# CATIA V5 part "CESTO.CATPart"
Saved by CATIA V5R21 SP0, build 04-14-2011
Part number: CESTO
Bounding box of the stored display mesh (mm): x -219.998 to 219.998, y -219.997 to 219.997, z -4 to 576
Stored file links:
  D:\MENA 3D\BISMARK\CESTO.CATPart
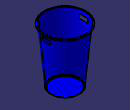
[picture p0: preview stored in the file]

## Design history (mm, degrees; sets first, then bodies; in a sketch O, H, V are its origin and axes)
Body1 (main body)
  Set1
    Sketch1 on yz-plane, origin (0, 0, 0), H (0, 1, 0), V (0, 0, 1)
      line L1 (0, 0) -> (136, 0)
      line L2 (136, 0) -> (136, -4)
      line L3 (136, -4) -> (138.75, -4)
      line L4 (138.75, -4) -> (138.75, 0)
      point P4 (138.75, 0)
      line L5 (138.75, 0) -> (146.5272, 0)
      arc A1 centre (146.5272, 6) radius 6 from (146.5272, 0) to (152.5, 5.4293) ccw
      point P7 (152.5, 5.4293)
      line L6 (152.5, 5.4293) -> (206.8226, 574)
      line L7 (206.8226, 574) -> (218, 574)
      line L8 (218, 574) -> (218, 565)
      line L9 (218, 565) -> (220, 565)
      line L10 (220, 565) -> (220, 576)
      line L11 (220, 576) -> (204, 576)
      point P13 (204, 576)
      line L12 (204, 576) -> (149.5136, 5.7147)
      arc A2 centre (147.6273, 5.8949) radius 1.8949 from (149.5136, 5.7147) to (147.6273, 4) cw
      line L13 (147.6273, 4) -> (0, 4)
      point P17 (0, 4)
      line L14 (0, 4) -> (0, 0)
      distance L14 L4 = 138.75
      distance L2 V = 136
      distance L3 L1 = 4
      distance L13 L1 = 4
      distance L11 L3 = 580
      length L10 = 11
      length L9 = 2
      length L8 = 9
      distance L6 L12 = 3
      distance L10 P13 = 16
      distance L10 V = 220
      distance P7 V = 152.5
      distance A2 A1 = 3
      radius A1 = 6
      horizontal: L1 H, L3 H, L5 H, L7 H, L9 H, L11 H, L13 H
      vertical: L2 V, L4 V, L8 V, L10 V, L14 V
      coincidence: P4 H, P17 V
      tangency: A1 L5, A2 L12, A1 L6, A2 L13
  Shaft1: profile Sketch1, axis Sketch1.V, angle 360
  Sketch2 on yz-plane, origin (0, 0, 0), H (0, 1, 0), V (0, 0, 1)
    point P1 (0, 514.5)
    line L1 (44.5, 526) -> (44.5, 503)
    line L2 (36.5, 495) -> (-36.5, 495)
    line L3 (-44.5, 503) -> (-44.5, 526)
    line L4 (-36.5, 534) -> (36.5, 534)
    reference projected line E1 (-138.75, -4) -> (138.75, -4) from edge [face of Shaft1 from Sketch1.L3 | face of Shaft1 from Sketch1.L4]
    arc A1 centre (36.5, 526) radius 8 from (44.5, 526) to (36.5, 534) ccw
    arc A2 centre (36.5, 503) radius 8 from (44.5, 503) to (36.5, 495) cw
    arc A3 centre (-36.5, 526) radius 8 from (-44.5, 526) to (-36.5, 534) cw
    arc A4 centre (-36.5, 503) radius 8 from (-36.5, 495) to (-44.5, 503) cw
    distance L2 E1 = 499
    distance L2 L4 = 39
    distance L3 L1 = 89
    radius A1 = 8
    radius A2 = 8
    radius A3 = 8
    radius A4 = 8
    coincidence: P1 V
    vertical: L1 V, L3 V
    horizontal: L2 H, L4 H
    equidistance: L1 L3 P1, L2 L4 P1
    tangency: A1 L1, A1 L4, A2 L1, A2 L2, A3 L3, A3 L4, A4 L2, A4 L3
  Pocket1: profile Sketch2, direction (-1, 0, 0), through (limit type 6), opposite side through (limit type 6)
